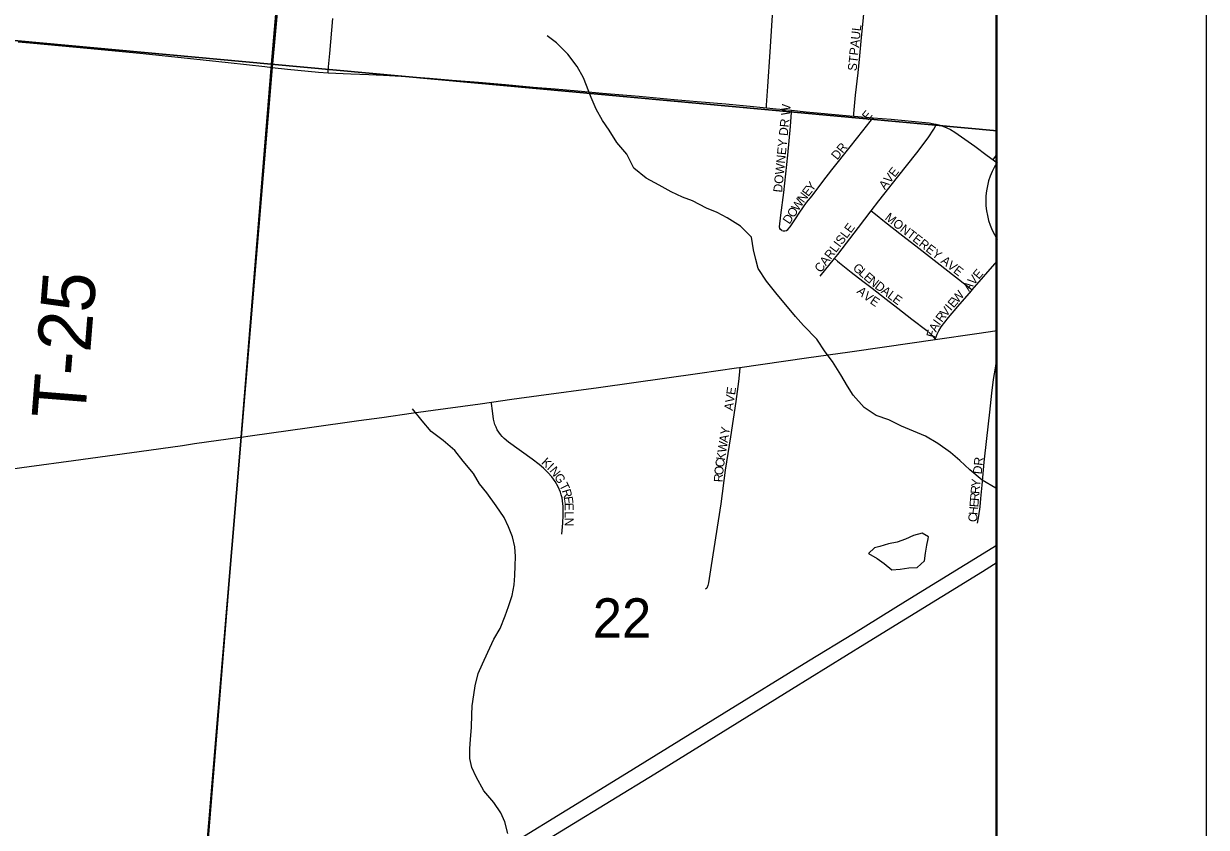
# Model space of a CAD drawing. Extents: x 0 to 680, y 0 to 440.
# Drawn here: x 268.81 to 288.52, y 309.46 to 322.85 of the extents above; entities that cross this region are included whole.
import ezdxf

# ---------------------------------------------------------------- set-up
doc = ezdxf.new("R2010")
doc.units = 0
for name, color, linetype in [('GM_X_Adjacent_County', 7, 'Continuous'), ('GM_X_County', 7, 'Continuous'), ('GM_X_County_Road', 7, 'Continuous'), ('GM_X_Minor_Lake', 7, 'Continuous'), ('GM_X_Minor_River', 7, 'Continuous'), ('GM_X_Section', 7, 'Continuous'), ('GM_X_Section_Text', 7, 'Continuous'), ('GM_X_State_Route', 7, 'Continuous'), ('GM_X_Township', 7, 'Continuous'), ('GM_X_Township_Road', 7, 'Continuous'), ('GM_X_Township_Road_Text', 7, 'Continuous'), ('GM_X_Township_Subdivision', 7, 'Continuous'), ('GM_X_Township_Subdivision_Text', 7, 'Continuous'), ('GM_X_Unincorporated', 7, 'Continuous'), ('GM_X_US_Route', 7, 'Continuous'), ('SH_Data', 7, 'Continuous'), ('SH_Text', 7, 'Continuous')]:
    doc.layers.add(name, color=color, linetype=linetype)

msp = doc.modelspace()

# ---------------------------------------------------------------- linework, layer by layer
at = {"layer": 'GM_X_Adjacent_County'}
msp.add_lwpolyline([(285.035, 209.752), (285.035, 415.359)], dxfattribs=at)
at = {"layer": 'GM_X_County'}
msp.add_lwpolyline([(285.035, 209.752), (285.035, 415.359)], dxfattribs=at)
at = {"layer": 'GM_X_County_Road'}
msp.add_line((284.966, 320.579), (285.035, 320.529), dxfattribs=at)
for points in [[(268.718, 322.547), (268.975, 322.524), (269.869, 322.44), (270.746, 322.356), (271.647, 322.262), (272.22, 322.201), (272.826, 322.134), (272.949, 322.12)], [(272.949, 322.12), (272.949, 322.12), (273.209, 322.091), (273.722, 322.041), (273.886, 322.028)], [(273.886, 322.028), (274.262, 322.013), (274.562, 322), (274.808, 321.99), (275.193, 321.967), (275.573, 321.94), (275.952, 321.908), (276.389, 321.873), (276.84, 321.833), (277.303, 321.793), (277.665, 321.763), (278.045, 321.727), (278.459, 321.693), (279.065, 321.641), (279.649, 321.588), (280.036, 321.553), (280.51, 321.512), (280.971, 321.469)], [(280.971, 321.469), (281.077, 321.46), (281.189, 321.447)], [(281.189, 321.447), (281.353, 321.429), (281.608, 321.405)], [(281.608, 321.405), (281.849, 321.381), (282.519, 321.319), (282.643, 321.309)], [(282.643, 321.309), (282.968, 321.281)], [(282.968, 321.281), (283.27, 321.255), (283.776, 321.21), (283.901, 321.195), (283.98, 321.181), (284.015, 321.173)], [(284.015, 321.173), (284.061, 321.162), (284.128, 321.141), (284.194, 321.115), (284.258, 321.085), (284.331, 321.041), (284.661, 320.807), (284.865, 320.654), (284.966, 320.579)]]:
    msp.add_lwpolyline(points, dxfattribs=at)
at = {"layer": 'GM_X_Minor_Lake'}
for points in [[(283.882, 314.263), (283.889, 314.299), (283.782, 314.359), (283.639, 314.319), (283.508, 314.256), (283.37, 314.21), (283.221, 314.182), (283.078, 314.136), (282.988, 314.113), (282.892, 314.019)], [(282.892, 314.019), (283.034, 313.934), (283.152, 313.855), (283.281, 313.747), (283.418, 313.757), (283.561, 313.779), (283.698, 313.784), (283.824, 313.895), (283.838, 314.026), (283.863, 314.156), (283.882, 314.263)]]:
    msp.add_lwpolyline(points, dxfattribs=at)
at = {"layer": 'GM_X_Minor_River'}
for points in [[(285.035, 315.087), (285.011, 315.106), (284.786, 315.239), (284.58, 315.414), (284.41, 315.571), (284.257, 315.704), (284.045, 315.855), (283.838, 315.976), (283.637, 316.056), (283.442, 316.141), (283.229, 316.245), (283.016, 316.319), (282.815, 316.452), (282.634, 316.656), (282.54, 316.806), (282.43, 316.998), (282.29, 317.219), (282.167, 317.381), (282.027, 317.591), (281.804, 317.82), (281.675, 317.97), (281.347, 318.366), (281.189, 318.559), (281.049, 318.768), (281.009, 318.918), (280.975, 319.079), (280.937, 319.293), (280.754, 319.474), (280.536, 319.613), (280.365, 319.704), (280.187, 319.772), (279.957, 319.894), (279.791, 319.955), (279.602, 320.047), (279.401, 320.156), (279.183, 320.277), (278.977, 320.441), (278.861, 320.674), (278.697, 320.866), (278.569, 321.076), (278.458, 321.238), (278.353, 321.423), (278.266, 321.621), (278.14, 321.944), (278.035, 322.135), (277.877, 322.339), (277.689, 322.532), (277.536, 322.647)], [(276.309, 315.351), (276.133, 315.561), (275.993, 315.736), (275.799, 315.904), (275.598, 316.055), (275.452, 316.23), (275.288, 316.428)], [(276.877, 309.351), (276.831, 309.548), (276.762, 309.698), (276.645, 309.871), (276.481, 310.064), (276.353, 310.297), (276.278, 310.452), (276.244, 310.601), (276.246, 310.768), (276.254, 310.922), (276.274, 311.124), (276.277, 311.332), (276.285, 311.481), (276.311, 311.665), (276.336, 311.813), (276.386, 312.021), (276.454, 312.18), (276.545, 312.375), (276.643, 312.594), (276.752, 312.771), (276.832, 312.979), (276.888, 313.138), (276.95, 313.322), (276.982, 313.5), (276.995, 313.654), (277.003, 313.815), (277.005, 313.969), (276.995, 314.13), (276.956, 314.297), (276.892, 314.464), (276.817, 314.62), (276.683, 314.812), (276.531, 315.028), (276.408, 315.178), (276.309, 315.351)]]:
    msp.add_lwpolyline(points, dxfattribs=at)
at = {"layer": 'GM_X_Section'}
for points in [[(258.466, 339.173), (274.289, 337.825), (272.932, 322.173), (257.365, 323.612)], [(285.035, 321.065), (285.035, 336.872), (274.289, 337.825), (272.932, 322.173)], [(257.365, 323.612), (272.932, 322.173), (271.613, 305.928), (256.695, 307.161)], [(285.035, 304.934), (285.035, 321.065), (272.932, 322.173), (271.613, 305.928)]]:
    msp.add_lwpolyline(points, close=True, dxfattribs=at)
at = {"layer": 'GM_X_State_Route'}
for points in [[(268.521, 303.985), (269.386, 304.529), (270.254, 305.067), (271.592, 305.89), (271.993, 306.137), (273.441, 307.03), (274.27, 307.538), (275.015, 307.997), (276.092, 308.66), (278.786, 310.315), (280.482, 311.363), (281.891, 312.23), (282.637, 312.688), (283.507, 313.223), (285.035, 314.165)], [(261.287, 299.13), (261.918, 299.536), (262.844, 300.109), (263.215, 300.339), (264.371, 301.067), (265.118, 301.538), (267.277, 302.907), (269.08, 304.045), (271.02, 305.251), (271.568, 305.588), (273.218, 306.603), (275.117, 307.768), (277.147, 309.013), (279.326, 310.349), (281.604, 311.761), (282.831, 312.515), (284.787, 313.72), (285.035, 313.873)]]:
    msp.add_lwpolyline(points, dxfattribs=at)
at = {"layer": 'GM_X_Township'}
for points in [[(285.035, 308.609), (285.035, 336.894)], [(267.852, 299.364), (268.864, 299.192), (269.338, 299.085), (269.962, 298.87), (270.974, 298.654), (271.355, 302.908), (271.568, 305.588), (271.592, 305.89), (272.434, 315.959), (272.949, 322.12), (273.328, 326.241)], [(273.328, 326.241), (272.949, 322.12), (272.434, 315.959), (271.592, 305.89)]]:
    msp.add_lwpolyline(points, dxfattribs=at)
at = {"layer": 'GM_X_Township_Road'}
for points in [[(281.189, 321.447), (281.191, 321.489), (281.21, 321.8), (281.25, 322.38), (281.302, 323.162), (281.339, 323.509), (281.361, 323.688)], [(273.886, 322.028), (273.891, 322.129), (273.91, 322.353), (273.962, 322.933)]]:
    msp.add_lwpolyline(points, dxfattribs=at)
at = {"layer": 'GM_X_Township_Subdivision'}
msp.add_line((284.617, 318.411), (285.035, 318.891), dxfattribs=at)
for points in [[(282.643, 321.309), (282.646, 321.351), (282.673, 321.655), (282.717, 322.028), (282.747, 322.315), (282.769, 322.559), (282.805, 322.95), (282.833, 323.243), (282.858, 323.555)], [(281.445, 319.402), (281.424, 319.419), (281.411, 319.436), (281.405, 319.461), (281.431, 319.656), (281.477, 320.037), (281.544, 320.656), (281.587, 321.133), (281.605, 321.375), (281.608, 321.405)], [(281.445, 319.402), (281.47, 319.394), (281.497, 319.395), (281.521, 319.402), (281.546, 319.42), (281.585, 319.465), (281.659, 319.581), (281.747, 319.708), (281.857, 319.867), (281.952, 319.982), (282.128, 320.217), (282.279, 320.411), (282.585, 320.794), (282.795, 321.065), (282.918, 321.218), (282.968, 321.281)], [(282.933, 319.729), (283.061, 319.898), (283.371, 320.291), (283.696, 320.698), (283.884, 320.946), (283.981, 321.091), (283.999, 321.13), (284.01, 321.159), (284.015, 321.173)], [(284.966, 320.579), (284.981, 320.599), (285.035, 320.673)], [(282.322, 318.937), (282.376, 319.003), (282.725, 319.453), (282.933, 319.729)], [(282.933, 319.729), (283.005, 319.672), (283.156, 319.552), (283.459, 319.312), (283.727, 319.106), (284.034, 318.871), (284.337, 318.631), (284.515, 318.492), (284.589, 318.434), (284.617, 318.411)], [(282.085, 318.643), (282.322, 318.937)], [(282.322, 318.937), (282.371, 318.894), (282.408, 318.862), (282.6, 318.709), (282.795, 318.559), (282.951, 318.439), (283.184, 318.259), (283.378, 318.107), (283.61, 317.925), (283.863, 317.734), (283.925, 317.683), (283.952, 317.651), (283.983, 317.612), (284.003, 317.586)], [(284.003, 317.586), (284.034, 317.674), (284.06, 317.728), (284.1, 317.799), (284.222, 317.952), (284.38, 318.138), (284.604, 318.397), (284.617, 318.411)], [(284.705, 314.523), (284.728, 314.65), (284.749, 314.797), (284.764, 314.935), (284.782, 315.16), (284.82, 315.539), (284.861, 315.935), (284.91, 316.374), (284.945, 316.692), (284.975, 316.919), (285.01, 317.142), (285.035, 317.328)], [(280.747, 317.122), (280.74, 317.046), (280.723, 316.884), (280.676, 316.553), (280.587, 315.966), (280.501, 315.406), (280.427, 314.849), (280.268, 313.821), (280.222, 313.533), (280.212, 313.486), (280.194, 313.441), (280.174, 313.423)], [(277.781, 314.344), (277.797, 314.523), (277.803, 314.656), (277.8, 314.801), (277.792, 314.899), (277.783, 314.948), (277.77, 314.996), (277.755, 315.042), (277.716, 315.133), (277.667, 315.218), (277.61, 315.298), (277.545, 315.372), (277.475, 315.441), (277.401, 315.504), (277.285, 315.592), (276.89, 315.873), (276.817, 315.934), (276.784, 315.967), (276.754, 316.003), (276.727, 316.042), (276.703, 316.083), (276.682, 316.125), (276.664, 316.169), (276.651, 316.214), (276.642, 316.261), (276.624, 316.395), (276.608, 316.52), (276.605, 316.54)]]:
    msp.add_lwpolyline(points, dxfattribs=at)
at = {"layer": 'GM_X_Unincorporated'}
msp.add_line((285.035, 319.26), (285.035, 320.538), dxfattribs=at)
msp.add_arc((286.009, 319.899), 1.165, 146.7392, 213.2608, dxfattribs=at)
at = {"layer": 'GM_X_US_Route'}
for points in [[(277.393, 316.651), (278.391, 316.788), (280.076, 317.027), (280.689, 317.113), (280.742, 317.121), (280.747, 317.122), (281.857, 317.281), (282.579, 317.38), (283.157, 317.461), (284.003, 317.586), (284.696, 317.688), (285.035, 317.735)], [(272.585, 315.98), (273.575, 316.12), (274.394, 316.236), (274.779, 316.288), (275.309, 316.362), (275.839, 316.434), (276.417, 316.513), (276.605, 316.54), (276.946, 316.589), (277.393, 316.651)], [(271.654, 315.85), (272.42, 315.957), (272.434, 315.959), (272.585, 315.98)], [(268.207, 315.375), (268.901, 315.47), (269.638, 315.57), (270.205, 315.647), (270.735, 315.722), (271.457, 315.822), (271.654, 315.85)]]:
    msp.add_lwpolyline(points, dxfattribs=at)
at = {"layer": 'SH_Data'}
for p, q in [((288.52, 418.859), (288.52, 173.859)), ((285.02, 415.359), (285.02, 177.359))]:
    msp.add_line(p, q, dxfattribs=at)
at = {"layer": 'SH_Text'}
for points in [[(47.02, 415.359), (285.02, 415.359), (285.02, 177.359), (47.02, 177.359)], [(285.019, 415.359), (47.02, 415.359), (47.02, 177.359), (285.019, 177.359)]]:
    msp.add_lwpolyline(points, close=True, dxfattribs=at)

# ---------------------------------------------------------------- texts
at = {"layer": 'GM_X_Section_Text'}
msp.add_text('22', height=0.6552, rotation=0, dxfattribs=at).set_placement((278.294, 312.618))
at = {"layer": 'GM_X_Township_Road_Text'}
msp.add_text('T-25', height=0.8894, rotation=85.4133, dxfattribs=at).set_placement((269.828, 316.239))
at = {"layer": 'GM_X_Township_Subdivision_Text'}
for s, height, rotation, p in [('PAUL', 0.1482, 83.6571, (282.714, 322.314)), ('ST', 0.1482, 82.88, (282.688, 322.054)), ('DOWNEY DR W', 0.14823, 84.3444, (281.449, 320.031)), ('E', 0.148, 50.3412, (282.881, 321.225)), ('DR', 0.1482, 50.7073, (282.368, 320.568)), ('AVE', 0.1482, 51.9537, (283.164, 320.072)), ('E', 0.148, 52.3814, (281.886, 319.957)), ('Y', 0.148, 52.2995, (281.949, 320.039)), ('W', 0.148, 56.198, (281.716, 319.713)), ('N', 0.148, 53.7332, (281.809, 319.852)), ('O', 0.148, 56.2614, (281.643, 319.604)), ('D', 0.148, 56.2796, (281.571, 319.496)), ('CARLISLE', 0.1482, 52.9576, (282.094, 318.689)), ('MONTEREY AVE', 0.14823, 322.3043, (283.151, 319.594)), ('G', 0.148, 319.5955, (282.617, 318.758)), ('L', 0.148, 319.6013, (282.716, 318.674)), ('E', 0.148, 49.4283, (284.727, 318.58)), ('E', 0.148, 319.6013, (282.796, 318.606)), ('N', 0.148, 320.3509, (282.877, 318.537)), ('D', 0.148, 322.9586, (282.983, 318.449)), ('V', 0.148, 49.6263, (284.643, 318.481)), ('A', 0.148, 319.4556, (282.683, 318.371)), ('V', 0.148, 323.4115, (282.791, 318.279)), ('A', 0.148, 323.4271, (283.088, 318.37)), ('L', 0.148, 323.4448, (283.193, 318.292)), ('E', 0.148, 323.4142, (283.277, 318.23)), ('W', 0.148, 49.2205, (284.375, 318.181)), ('A', 0.148, 53.1563, (284.566, 318.378)), ('E', 0.148, 326.0745, (282.902, 318.197)), ('V', 0.148, 50.2616, (284.182, 317.953)), ('I', 0.148, 49.4224, (284.265, 318.053)), ('E', 0.148, 49.2357, (284.307, 318.102)), ('R', 0.148, 52.7512, (284.112, 317.861)), ('F', 0.148, 74.8838, (283.993, 317.605)), ('A', 0.148, 62.4185, (284.017, 317.698)), ('I', 0.148, 54.3099, (284.074, 317.809)), ('AVE', 0.1482, 81.8666, (280.627, 316.393)), ('A', 0.148, 80.888, (280.542, 315.859)), ('Y', 0.148, 80.8683, (280.563, 315.988)), ('W', 0.148, 80.8591, (280.515, 315.692)), ('K', 0.148, 317.319, (277.426, 315.523)), ('C', 0.148, 81.3203, (280.477, 315.447)), ('K', 0.148, 80.8683, (280.495, 315.563)), ('DR', 0.1482, 83.9946, (284.775, 315.335)), ('I', 0.148, 316.5766, (277.521, 315.435)), ('N', 0.148, 309.3186, (277.565, 315.394)), ('O', 0.148, 84.6156, (280.465, 315.32)), ('G', 0.148, 302.3019, (277.645, 315.297)), ('T', 0.148, 296.785, (277.732, 315.155)), ('R', 0.148, 86.3055, (280.458, 315.204)), ('Y', 0.148, 83.8915, (284.746, 315.123)), ('R', 0.148, 287.1599, (277.776, 315.068)), ('R', 0.148, 85.1759, (284.727, 314.89)), ('R', 0.148, 85.1865, (284.737, 315.007)), ('E', 0.148, 278.0605, (277.81, 314.962)), ('E', 0.148, 271.3932, (277.824, 314.863)), ('H', 0.148, 85.1637, (284.707, 314.656)), ('E', 0.148, 85.1592, (284.718, 314.786)), ('L', 0.148, 269.9956, (277.826, 314.721)), ('N', 0.148, 269.9928, (277.826, 314.616)), ('C', 0.148, 85.1617, (284.697, 314.539))]:
    msp.add_text(s, height=height, rotation=rotation, dxfattribs=at).set_placement(p)

doc.saveas('drawing.dxf')
